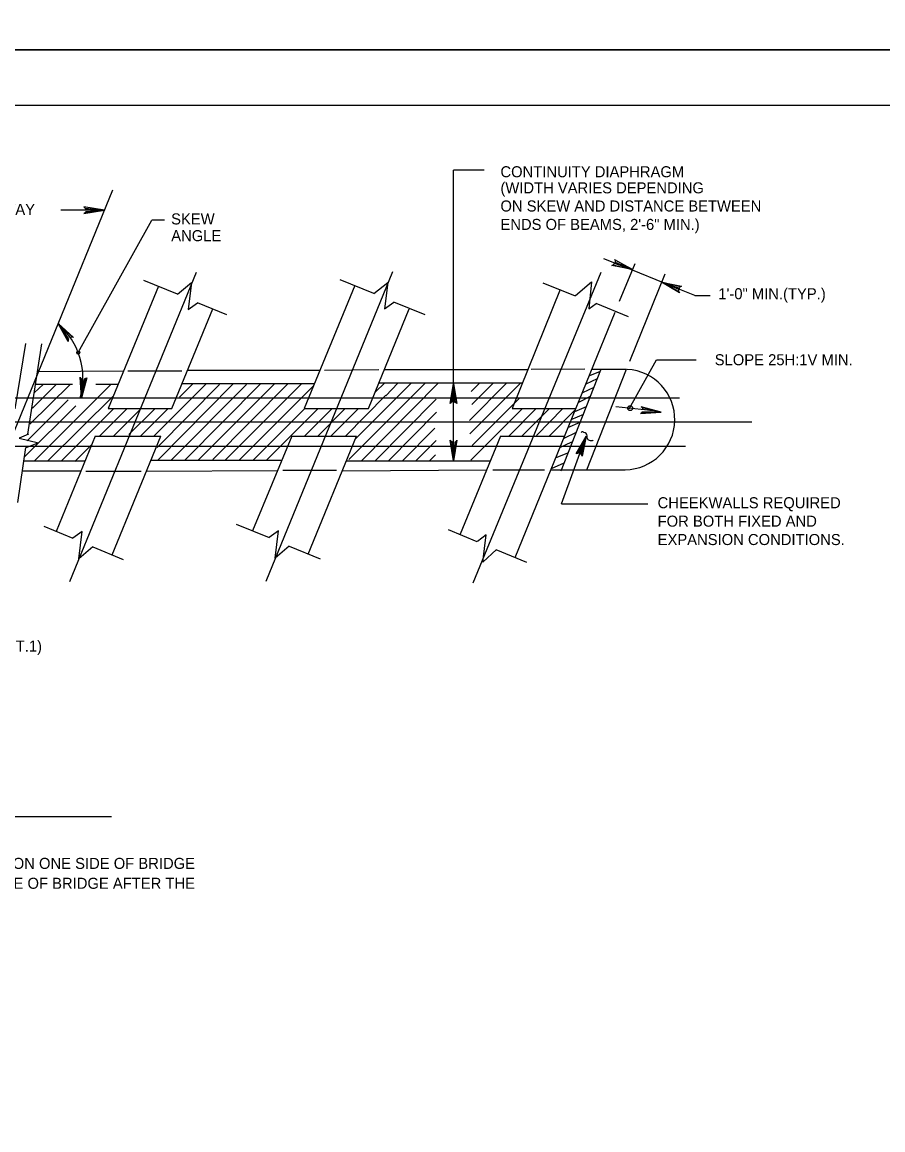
# Model space of a CAD drawing. Extents: x 641517 to 642372, y 298537 to 300319.
# Drawn here: x 641794.6 to 642028.2, y 298837.4 to 299138.1 of the extents above; entities that cross this region are included whole.
import ezdxf

# ---------------------------------------------------------------- set-up
doc = ezdxf.new("R2010")
doc.units = 0
for name, color, linetype in [('2', 7, 'Continuous'), ('3', 7, 'Continuous'), ('PLT-BNDY', 7, 'Continuous')]:
    doc.layers.add(name, color=color, linetype=linetype)

msp = doc.modelspace()

# ---------------------------------------------------------------- linework, layer by layer
at = {"layer": '2'}
for p, q in [((641557.05, 299115.62), (642343.05, 299115.62)), ((641911.66, 299039.94), (641911.66, 299097.9)), ((641919.94, 299097.9), (641911.66, 299097.9)), ((641773.78, 298981.44), (641819.22, 299092.64)), ((641816.93, 299087.05), (641805.05, 299087.05)), ((641809.78, 299048.4), (641829.76, 299084.4)), ((641833.18, 299084.4), (641829.76, 299084.4)), ((641960.23, 299070.76), (641952.49, 299073.82)), ((641956.67, 299062.41), (641960.95, 299072.56)), ((641841.82, 299070.18), (641807.44, 298986.12)), ((641895.1, 299070.36), (641860.72, 298986.3)), ((641951.62, 299070.18), (641916.88, 298985.76)), ((641959.54, 299046.06), (641969.09, 299069.83)), ((641968.69, 299067.34), (641960.23, 299070.76)), ((641831.56, 299066.4), (641817.94, 299033.25)), ((641836.78, 299064.24), (641827.6, 299068.02)), ((641884.84, 299066.58), (641871.15, 299033.25)), ((641890.06, 299064.42), (641880.88, 299068.2)), ((641944.78, 299063.7), (641935.96, 299067.3)), ((641977.15, 299063.92), (641968.15, 299067.52)), ((641940.64, 299065.5), (641927.62, 299033.25)), ((641977.15, 299063.92), (641981.29, 299063.92)), ((641835.22, 299033.25), (641846.32, 299060.28)), ((641850.1, 299058.66), (641842.18, 299061.9)), ((641888.61, 299033.25), (641899.6, 299060.28)), ((641903.92, 299058.66), (641895.46, 299062.08)), ((641959.18, 299058.12), (641950.36, 299061.72)), ((641928.4, 298992.78), (641955.58, 299059.38)), ((641792.68, 299033.1), (641795.56, 299050.92)), ((641796.1, 299026.26), (641799.88, 299050.74)), ((641959.36, 299033.1), (641966.74, 299046.42)), ((641966.74, 299046.42), (641977.54, 299046.42)), ((641822.02, 299043.36), (641798.8, 299043.18)), ((641837.93, 299043.36), (641823.27, 299043.36)), ((641875.38, 299043.54), (641839.48, 299043.54)), ((641891.39, 299043.69), (641876.61, 299043.58)), ((641931.85, 299043.72), (641892.87, 299043.72)), ((641947.33, 299043.89), (641932.77, 299043.78)), ((641940.86, 299016.32), (641951.66, 299043.68)), ((641947.84, 299016.54), (641958.64, 299043.9)), ((641951.48, 299043.23), (641948.56, 299042.1)), ((641949.28, 299043.9), (641958.64, 299043.9)), ((641808.27, 299039.76), (641798.26, 299039.76)), ((641820.58, 299039.76), (641814.59, 299039.76)), ((641873.86, 299039.94), (641838.04, 299039.94)), ((641930.38, 299040.12), (641891.32, 299040.12)), ((641911.66, 299019.06), (641911.66, 299039.94)), ((641946.76, 299037.6), (641949.82, 299039.02)), ((641947.66, 299039.94), (641950.75, 299041.37)), ((641640.61, 299036.16), (641973.04, 299036.16)), ((641945.5, 299034.9), (641948.86, 299036.58)), ((641817.94, 299033.25), (641835.22, 299033.25)), ((641871.15, 299033.25), (641888.61, 299033.25)), ((641927.62, 299033.25), (641944.92, 299033.25)), ((641947.71, 299033.72), (641944.53, 299032.36)), ((641966.02, 299032.56), (641955.76, 299033.64)), ((641943.62, 299030.25), (641946.99, 299031.69)), ((641992.66, 299029.5), (641739.33, 299029.5)), ((641941.72, 299025.18), (641945.01, 299026.83)), ((641942.72, 299028.08), (641946.06, 299029.51)), ((641814.4, 299025.76), (641803.84, 298999.8)), ((641814.4, 299025.76), (641832.22, 299025.76)), ((641818.96, 298993.5), (641832.22, 299025.76)), ((641867.79, 299025.76), (641857.12, 298999.98)), ((641867.79, 299025.76), (641885.34, 299025.76)), ((641872.24, 298993.68), (641885.34, 299025.76)), ((641924.38, 299025.76), (641913.46, 298999.08)), ((641924.38, 299025.76), (641941.86, 299025.76)), ((641940.54, 299022.63), (641943.82, 299024.15)), ((641941, 299007.36), (641947.66, 299025.72)), ((641685.2, 299023.02), (641974.66, 299023.02)), ((641793.4, 299007.72), (641795.56, 299022.66)), ((641939.36, 299019.79), (641942.65, 299021.2)), ((641795.02, 299019.06), (641811.76, 299019.06)), ((641829.4, 299019.24), (641865.04, 299019.24)), ((641882.68, 299019.06), (641921.74, 299019.06)), ((641938.3, 299016.9), (641941.72, 299018.5)), ((641810.5, 299016.18), (641794.66, 299016.18)), ((641811.88, 299016.18), (641826.88, 299016.18)), ((641828.32, 299016.18), (641863.91, 299016.38)), ((641879.89, 299016.36), (641865.34, 299016.36)), ((641881.5, 299016.34), (641920.63, 299016.58)), ((641922.29, 299016.54), (641936.39, 299016.54)), ((641938.1, 299016.54), (641958.28, 299016.54)), ((641941, 299007.36), (641964.4, 299007.36)), ((641800.42, 299001.24), (641808.34, 298998)), ((641852.62, 299001.78), (641861.62, 298998.18)), ((641910.22, 299000.34), (641917.96, 298997.1)), ((641813.74, 298995.66), (641822.02, 298992.24)), ((641867.02, 298995.84), (641875.48, 298992.42)), ((641923.18, 298994.94), (641931.46, 298991.52)), ((641701.22, 298922.48), (641818.84, 298922.48))]:
    msp.add_line(p, q, dxfattribs=at)
for points in [[(641811.71, 299086.33), (641811.89, 299086.69), (641816.93, 299087.05), (641811.71, 299086.33), (641811.35, 299086.15), (641816.93, 299087.05), (641811.89, 299087.23), (641811.71, 299087.59), (641816.93, 299087.05), (641811.35, 299087.95), (641811.71, 299087.59)], [(641811.71, 299086.33), (641811.89, 299086.69), (641816.93, 299087.05), (641811.71, 299086.33), (641811.35, 299086.15), (641816.93, 299087.05), (641811.89, 299087.23), (641811.71, 299087.59), (641816.93, 299087.05), (641811.35, 299087.95), (641811.71, 299087.59)], [(641955.55, 299073.46), (641955.55, 299072.92), (641960.23, 299070.94), (641955.55, 299073.46), (641955.37, 299073.64), (641960.23, 299070.94), (641955.37, 299072.56), (641955.01, 299072.2), (641960.23, 299070.94), (641954.65, 299072.02), (641955.01, 299072.2)], [(641836.78, 299064.24), (641840.56, 299067.48), (641839.66, 299060.1), (641842.18, 299061.9)], [(641890.06, 299064.42), (641893.84, 299067.48), (641892.94, 299060.28), (641895.46, 299062.08)], [(641944.78, 299063.88), (641949.1, 299067.66), (641948.38, 299060.28), (641950.36, 299061.72)], [(641972.83, 299065), (641972.83, 299065.54), (641968.15, 299067.52), (641972.83, 299065), (641973.01, 299064.64), (641968.15, 299067.52), (641973.01, 299065.9), (641973.19, 299066.26), (641968.15, 299067.52), (641973.55, 299066.44), (641973.19, 299066.26)], [(641807.08, 299051.82), (641807.26, 299052.18), (641804.38, 299056.32), (641807.08, 299051.82), (641807.08, 299051.46), (641804.38, 299056.32), (641807.62, 299052.54), (641808.16, 299052.72), (641804.38, 299056.32), (641808.52, 299052.54), (641808.16, 299052.72)], [(641811.76, 299041.38), (641811.4, 299041.2), (641810.68, 299036.16), (641811.76, 299041.38), (641812.12, 299041.56), (641810.68, 299036.16), (641810.86, 299041.2), (641810.5, 299041.38), (641810.68, 299036.16), (641810.32, 299041.74), (641810.5, 299041.38)], [(641796.64, 299028.96), (641807.62, 299039.76)], [(641797.36, 299033.28), (641803.84, 299039.76)], [(641797.9, 299019.06), (641818.6, 299039.76)], [(641797.9, 299037.6), (641800.24, 299039.76)], [(641831.2, 299022.66), (641848.13, 299039.77)], [(641831.38, 299019.24), (641851.76, 299039.8)], [(641834.98, 299019.24), (641855.49, 299039.75)], [(641837.24, 299036.27), (641840.92, 299039.94)], [(641838.76, 299019.24), (641859.33, 299039.99)], [(641839.96, 299035.38), (641844.39, 299039.82)], [(641842.42, 299019.31), (641863.06, 299039.94)], [(641846.29, 299019.39), (641866.66, 299039.94)], [(641849.71, 299019.21), (641870.44, 299039.94)], [(641853.52, 299019.24), (641873.68, 299039.4)], [(641883.22, 299019.42), (641903.92, 299040.12)], [(641885.05, 299025.03), (641900.14, 299040.12)], [(641886.64, 299019.06), (641907.52, 299040.12)], [(641890.45, 299037.79), (641892.94, 299040.12)], [(641893.3, 299036.7), (641896.54, 299040.12)], [(641910.94, 299034.9), (641911.3, 299035.08), (641911.66, 299039.94), (641910.94, 299034.9), (641910.76, 299034.54), (641911.66, 299039.94), (641911.84, 299035.08), (641912.2, 299034.9), (641911.66, 299039.94), (641912.56, 299034.54), (641912.2, 299034.9)], [(641916, 299029.98), (641926.06, 299040.12)], [(641916.08, 299026.36), (641929.84, 299040.12)], [(641916.46, 299037.88), (641918.68, 299040.12)], [(641916.65, 299034.31), (641922.46, 299040.12)], [(641801.5, 299019.06), (641819.32, 299036.7)], [(641882.34, 299025.76), (641893.3, 299036.88)], [(641890.42, 299019.06), (641906.96, 299035.75)], [(641916.7, 299023.2), (641929.48, 299035.98)], [(641795.2, 299020.14), (641809.12, 299033.93)], [(641795.92, 299024.46), (641807.02, 299035.57)], [(641810.68, 299024.46), (641819.47, 299033.25)], [(641815.57, 299025.76), (641823.07, 299033.25)], [(641819.35, 299025.76), (641826.85, 299033.25)], [(641823.55, 299026.18), (641830.63, 299033.25)], [(641826.73, 299025.76), (641834.23, 299033.25)], [(641830.33, 299025.76), (641840.25, 299035.68)], [(641857.3, 299019.24), (641871.31, 299033.25)], [(641867.41, 299025.76), (641874.91, 299033.25)], [(641871.19, 299025.76), (641878.69, 299033.25)], [(641874.79, 299025.76), (641882.29, 299033.25)], [(641878.39, 299025.76), (641885.89, 299033.25)], [(641916.34, 299019.24), (641930.35, 299033.25)], [(641926.63, 299025.76), (641934.13, 299033.25)], [(641930.23, 299025.76), (641937.73, 299033.25)], [(641934.16, 299025.9), (641941.32, 299033.25)], [(641937.61, 299025.76), (641944.78, 299032.93)], [(641962.78, 299032.02), (641962.96, 299032.38), (641968, 299032.2), (641962.78, 299032.02), (641962.42, 299031.84), (641968, 299032.2), (641963.14, 299032.92), (641962.96, 299033.46), (641968, 299032.2), (641962.6, 299033.64), (641962.96, 299033.46)], [(641894.02, 299019.06), (641907.08, 299032.23)], [(641897.8, 299019.06), (641906.57, 299027.91)], [(641796.28, 299026.26), (641793.76, 299025.18), (641798.98, 299023.92), (641795.38, 299022.48)], [(641805.28, 299019.06), (641810.86, 299024.64)], [(641861.98, 299020.32), (641868.05, 299026.39)], [(641901.4, 299019.06), (641906.92, 299024.58)], [(641912.38, 299024.28), (641912.02, 299024.1), (641911.66, 299019.06), (641912.38, 299024.28), (641912.56, 299024.64), (641911.66, 299019.06), (641911.48, 299024.1), (641911.12, 299024.28), (641911.66, 299019.06), (641910.76, 299024.64), (641911.12, 299024.28)], [(641916.97, 299023.48), (641917.24, 299023.74)], [(641945.14, 299021.04), (641945.68, 299021.22), (641947.66, 299025.72), (641945.14, 299021.04), (641944.96, 299021.04), (641947.66, 299025.72), (641946.04, 299021.04), (641946.4, 299020.68), (641947.66, 299025.72), (641946.58, 299020.32), (641946.4, 299020.68)], [(641808.88, 299018.88), (641813.56, 299023.56)], [(641860.9, 299019.24), (641862.52, 299020.86)], [(641905.18, 299019.06), (641906.74, 299020.64)], [(641813.74, 298995.66), (641809.96, 298992.42), (641810.86, 298999.8), (641808.34, 298998)], [(641867.02, 298995.84), (641863.24, 298992.6), (641864.14, 298999.98), (641861.62, 298998.18)], [(641923.36, 298994.94), (641919.58, 298991.52), (641920.48, 298998.9), (641918.14, 298997.1)]]:
    msp.add_lwpolyline(points, dxfattribs=at)
for centre, radius in [((641809.78, 299048.4), 0.406), ((641959.61, 299033.32), 0.65)]:
    msp.add_circle(centre, radius, dxfattribs=at)
for centre, radius, start, end in [((641791.2, 299041.35), 19.87, 344.6208, 48.6198), ((641958.11, 299030.23), 13.62, 270.6015, 86.9793)]:
    msp.add_arc(centre, radius, start, end, dxfattribs=at)
msp.add_spline([(641949.6, 299024.63), (641949.3, 299024.48), (641948.4, 299024.63), (641947.95, 299025.23), (641947.95, 299025.83), (641947.65, 299026.43), (641947.05, 299026.73), (641946.75, 299026.88), (641946.3, 299026.73)], degree=3, dxfattribs=at)
at = {"layer": 'PLT-BNDY'}
for points in [[(641517.05, 299724.62), (642358.05, 299724.62), (642358.05, 299130.62), (641517.05, 299130.62)], [(641517.05, 299130.62), (642358.05, 299130.62), (642358.05, 298536.62), (641517.05, 298536.62)]]:
    msp.add_lwpolyline(points, close=True, dxfattribs=at)

# ---------------------------------------------------------------- texts
at = {"layer": '2'}
for s, height, p in [('  OF ROADWAY', 2.9998, (641768.43, 299085.79)), ('SKEW', 3, (641835.01, 299083.2)), ('ANGLE', 3, (641835.03, 299078.65)), ('1\'-0" MIN.(TYP.)', 2.9998, (641983.54, 299062.89)), ('SLOPE 25H:1V MIN.', 2.9996, (641982.56, 299044.97)), ('CHEEKWALLS REQUIRED', 2.9998, (641967.06, 299006.14)), ('FOR BOTH FIXED AND', 2.9998, (641967.06, 299001.14)), ('EXPANSION CONDITIONS.', 2.9998, (641967.06, 298996.15)), ('(SEE NOTE 10 ON SHT.1)', 3, (641751.81, 298967.21)), ('ADJACENT BOX BEAM BRIDGES ARE SIMILAR. PLACE CHEEKWALLS ON ONE SIDE OF BRIDGE', 3, (641658.03, 298908.22)), ('BEFORE THE BEAMS ARE SET.  PLACE CHEEKWALLS ON OTHER SIDE OF BRIDGE AFTER THE', 3, (641658.03, 298902.82))]:
    msp.add_text(s, height=height, dxfattribs=at).set_placement(p)
at = {"layer": '3'}
for s, p in [('CONTINUITY DIAPHRAGM', (641924.4, 299096.01)), ('(WIDTH VARIES DEPENDING', (641924.4, 299091.64)), ('ON SKEW AND DISTANCE BETWEEN', (641924.4, 299086.71)), ('ENDS OF BEAMS, 2\'-6" MIN.)', (641924.4, 299081.71))]:
    msp.add_text(s, height=2.9969, dxfattribs=at).set_placement(p)

doc.saveas('drawing.dxf')
